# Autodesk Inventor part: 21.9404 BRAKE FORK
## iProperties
Created: 2010-10
Part Number: 21.9404 BRAKE FORK
Document SubType Name: Modeling
Designer: Administrator
Density: 7.85 g/cm^3
Material: Steel
Mass: 84.9184 g
Surface Area: 153.822 cm^2
Volume: 10.8176 cm^3
Author: Administrator
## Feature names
1. Base1
